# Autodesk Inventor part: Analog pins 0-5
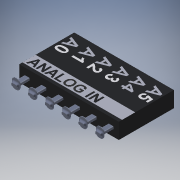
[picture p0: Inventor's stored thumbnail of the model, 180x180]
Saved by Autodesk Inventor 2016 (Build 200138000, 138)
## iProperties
Created: 2018-03
Part Number: Analog pins 0-5
Material: Générique
Document SubType Name: Modeling
Designer: Bruno
Density: 1 g/cm^3
Appearance: Par défaut
Author: Bruno
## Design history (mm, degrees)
feature "Composite1"
body "Srf1"
